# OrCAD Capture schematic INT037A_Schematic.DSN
size A; title: TUSB211PICO-EVM INT037; rev: A
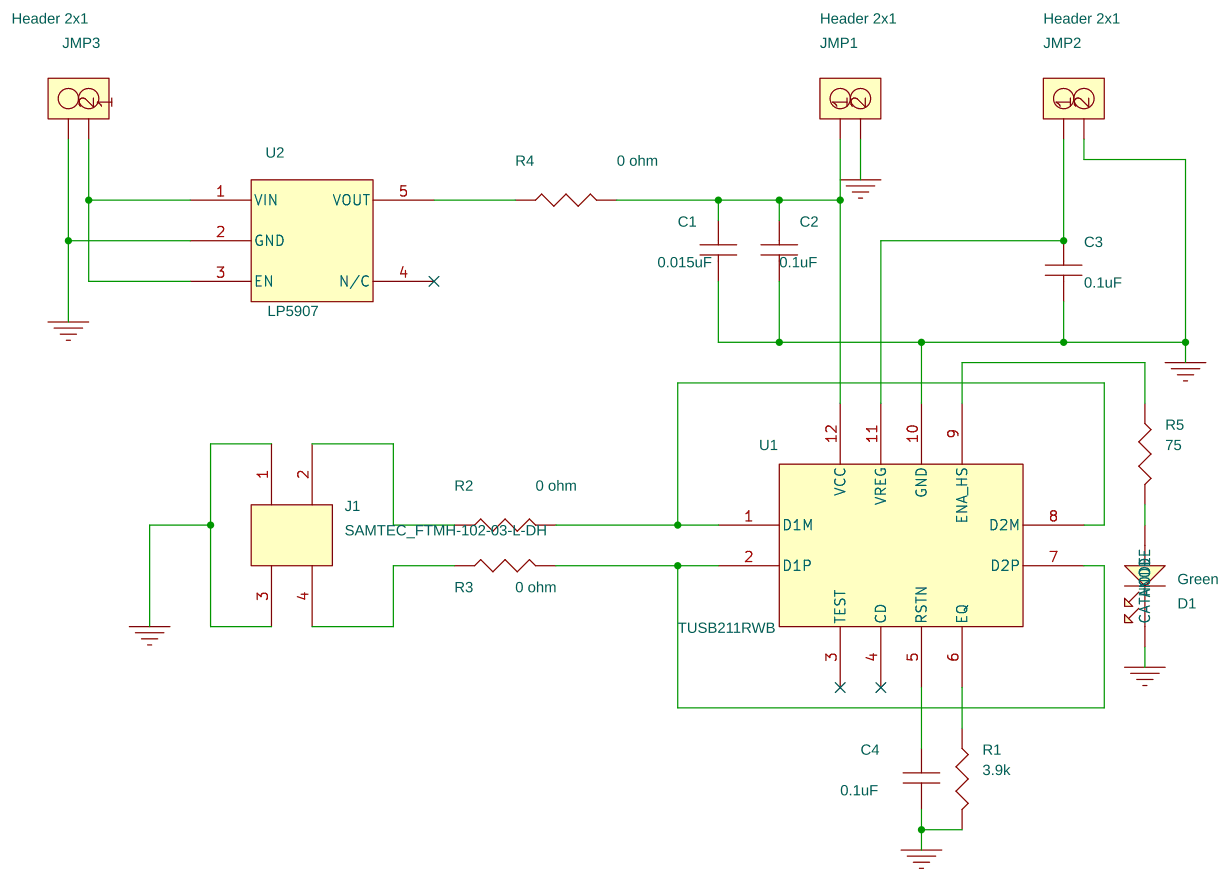
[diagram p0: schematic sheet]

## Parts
C1  0.015uF  [0402]
C2  0.1uF  [0402]
C3  0.1uF  [0402]
C4  0.1uF  [0402]
D1  Green  [LED_LTST-C190KGKT]
J1  SAMTEC_FTMH-102-03-L-DH  [HDR_SMRT_2x2_39_FTMH]
JMP1  Header 2x1  [HDR_THVT_1x2_100]
JMP2  Header 2x1  [HDR_THVT_1x2_100]
JMP3  Header 2x1  [HDR_THVT_1x2_100]
R1  3.9k  [0402]
R2  0 ohm  [0201]
R3  0 ohm  [0201]
R4  0 ohm  [0402]
R5  75  [0402]
U1  TUSB211RWB  [RWB]
U2  LP5907  [DBV_R-PDSO-G5]

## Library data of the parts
C1-C4 = cc0402
D1 = Green_LED
J1 = SAMTEC_HDR
JMP1-JMP3 = Header_2x1
R1 R4 R5 = r0402
R2 R3 = r0201
U1 = TUSB211RWB
U2 = LP5907

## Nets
GND: C1.2 C2.2 C3.2 C4.2 D1.1(CATHODE) J1.1 J1.3 JMP1.2 JMP2.2 JMP3.2 R1.2 U1.10(GND) U2.2(GND)
N00271: R3.2 U1.2(D1P) U1.7(D2P)
N00296: R2.2 U1.1(D1M) U1.8(D2M)
N00343: C3.1 JMP2.1 U1.11(VREG)
N00391: C1.1 C2.1 JMP1.1 R4.2 U1.12(VCC)
N00931: C4.1 U1.5(RSTN)
N00935: R1.1 U1.6(EQ)
N16589199: JMP3.1 U2.1(VIN) U2.3(EN)
N16589333: R4.1 U2.5(VOUT)
N16590097: J1.2 R2.1
N16590109: J1.4 R3.1
N16590469: R5.1 U1.9(ENA_HS)
N16590481: D1.2(ANODE) R5.2

Not connected (* = marked no-connect by the designer): U1 3(TEST)* 4(CD)*; U2 4(N/C)*
